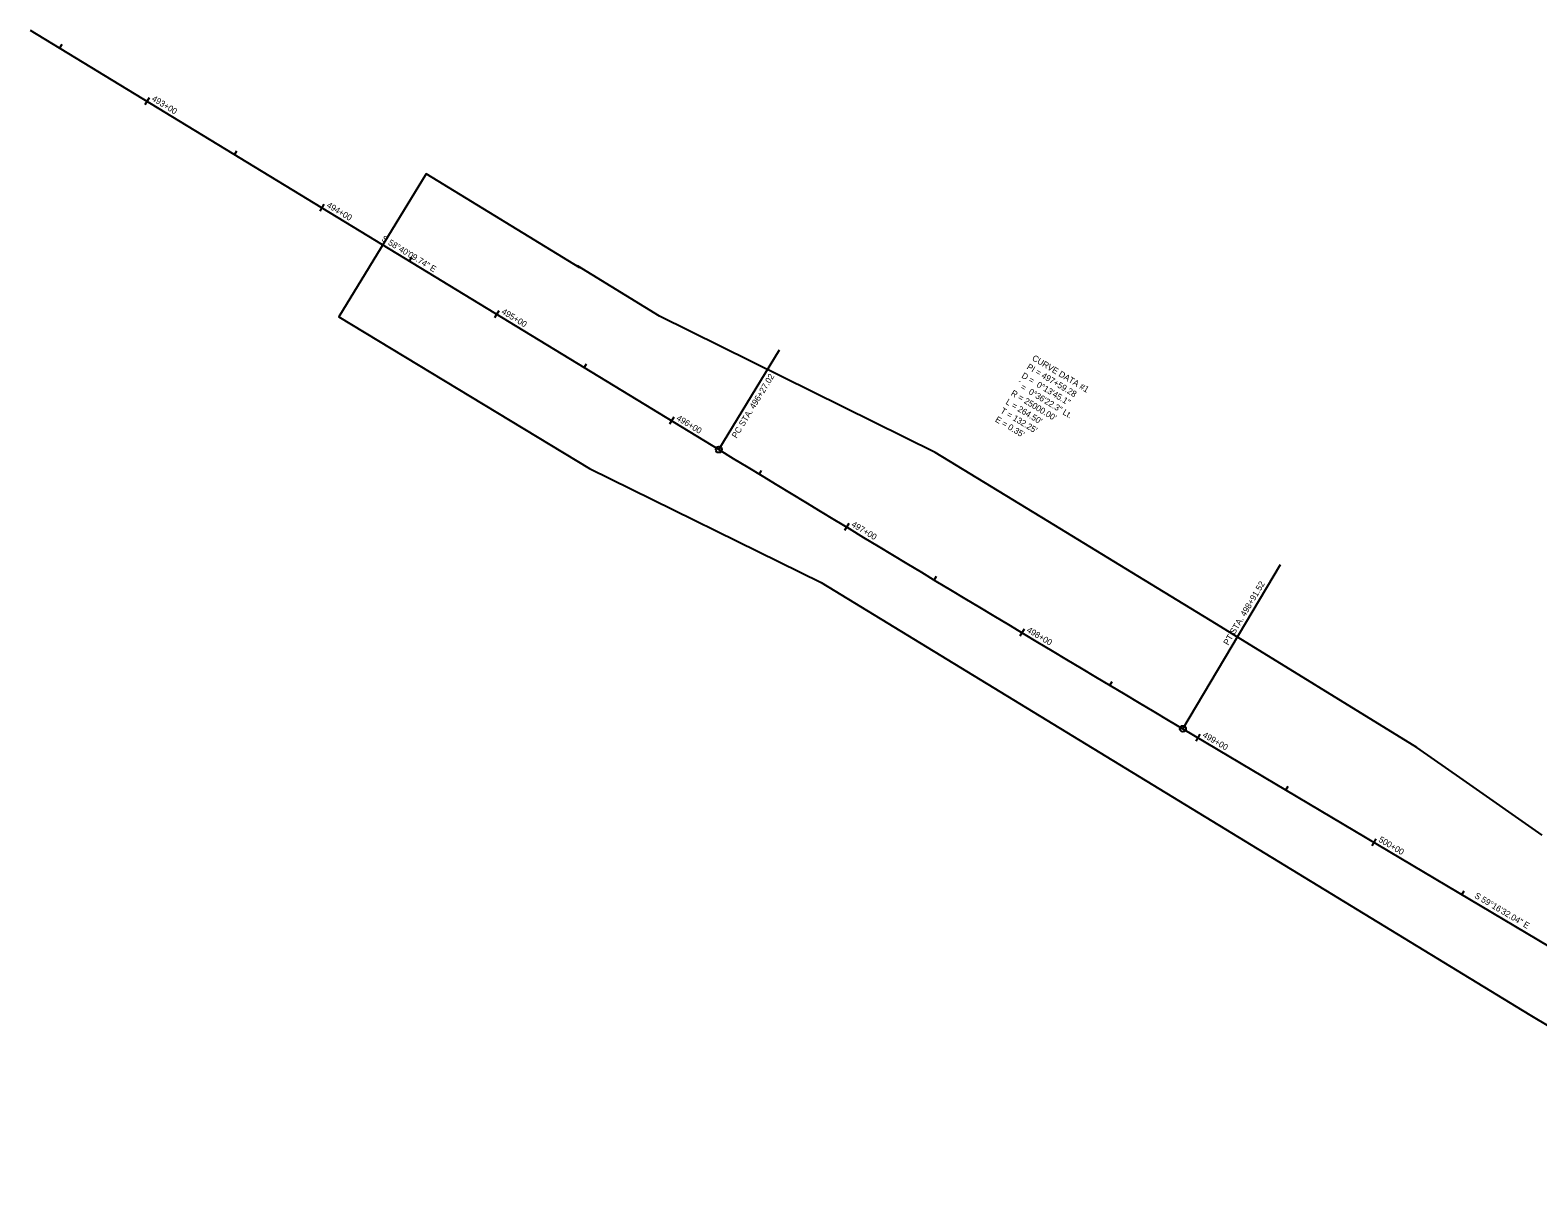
# Model space of a CAD drawing. Extents: x 1743277 to 1746745, y 462828 to 464839.
# Drawn here: x 1743277 to 1744013, y 464280 to 464839 of the extents above; entities that cross this region are included whole.
import ezdxf

# ---------------------------------------------------------------- set-up
doc = ezdxf.new("R2010")
doc.units = 0
for name, color, linetype in [('D_Roadway_Centerline', 7, 'Continuous'), ('D_Roadway_Centerline_Bearings', 7, 'Continuous'), ('D_Roadway_Centerline_CurveData', 7, 'Continuous'), ('D_Roadway_Centerline_Flags', 7, 'Continuous'), ('D_Roadway_Centerline_Text', 7, 'Continuous'), ('D_Roadway_Edge_TW', 7, 'Continuous')]:
    doc.layers.add(name, color=color, linetype=linetype)

msp = doc.modelspace()

# ---------------------------------------------------------------- linework, layer by layer
at = {"layer": 'D_Roadway_Centerline'}
for p, q in [((1743276.84, 464839.33), (1743613.24, 464634.55)), ((1743839.9, 464498.21), (1744191.04, 464289.52)), ((1743839.9, 464498.21), (1744191.04, 464289.52))]:
    msp.add_line(p, q, dxfattribs=at)
msp.add_arc((1756612.64, 485989.07), 25000, 238.669373, 239.275565, dxfattribs=at)
at = {"layer": 'D_Roadway_Centerline_Flags'}
for points in [[(1743613.24, 464634.55), (1743642.87, 464683.21)], [(1743839.9, 464498.21), (1743887.58, 464578.44)]]:
    msp.add_lwpolyline(points, dxfattribs=at)
for centre in [(1743613.24, 464634.55), (1743839.9, 464498.21)]:
    msp.add_circle(centre, 1.5, dxfattribs=at)
at = {"layer": 'D_Roadway_Centerline_Text'}
for points in [[(1743292.24, 464832.3), (1743291.2, 464830.59)], [(1743334.95, 464806.3), (1743332.87, 464802.88)], [(1743377.65, 464780.3), (1743376.61, 464778.59)], [(1743420.36, 464754.3), (1743418.28, 464750.89)], [(1743463.07, 464728.3), (1743462.03, 464726.6)], [(1743505.78, 464702.31), (1743503.7, 464698.89)], [(1743548.49, 464676.31), (1743547.45, 464674.6)], [(1743591.2, 464650.31), (1743589.12, 464646.89)], [(1743633.91, 464624.32), (1743632.87, 464622.61)], [(1743676.67, 464598.4), (1743674.6, 464594.98)], [(1743719.48, 464572.58), (1743718.44, 464570.86)], [(1743762.33, 464546.83), (1743760.28, 464543.4)], [(1743805.24, 464521.17), (1743804.22, 464519.46)], [(1743848.21, 464495.6), (1743846.16, 464492.16)], [(1743891.19, 464470.06), (1743890.17, 464468.34)], [(1743934.17, 464444.51), (1743932.13, 464441.07)], [(1743977.15, 464418.96), (1743976.13, 464417.25)]]:
    msp.add_lwpolyline(points, dxfattribs=at)
at = {"layer": 'D_Roadway_Edge_TW'}
for q in [(1743470.2, 464769.13), (1743544.26, 464724.3)]:
    msp.add_line((1743545.32, 464723.24), q, dxfattribs=at)
for points in [[(1743470.2, 464769.13), (1743427.68, 464699.28), (1743550.04, 464625.23), (1743663.29, 464569.56), (1744009.39, 464358.55), (1744096.94, 464306.36), (1744135.34, 464282.83), (1744151.41, 464265.42), (1744426.2, 464103.29), (1744481.09, 464065.93), (1744521.09, 464032.86), (1744582.5, 463969.09), (1744608.78, 463934.83), (1744633.67, 463900.81), (1744642.64, 463879.56)], [(1744015.47, 464446.22), (1743976.84, 464473.32), (1743954.23, 464489.03), (1743856.27, 464549.26), (1743814.95, 464574.53), (1743773.93, 464599.6), (1743718.97, 464633.17), (1743584.2, 464699.66), (1743544.26, 464724.3)]]:
    msp.add_lwpolyline(points, dxfattribs=at)

# ---------------------------------------------------------------- texts
at = {"layer": 'D_Roadway_Centerline_Bearings'}
for s, rotation, p in [('S 58%%d40\'09.74" E', 328.66937, (1743448.18, 464736.76)), ('S 59%%d16\'32.04" E', 329.27557, (1743982.04, 464415.91))]:
    msp.add_text(s, height=3, rotation=rotation, dxfattribs=at).set_placement(p)
at = {"layer": 'D_Roadway_Centerline_CurveData'}
for s, p in [('PI = 497+59.28', (1743763.37, 464674.13)), ('CURVE DATA #1', (1743765.95, 464678.41)), ('D =  0%%d13\'45.1"', (1743760.8, 464669.84)), ("R = 25000.00'", (1743755.64, 464661.27)), ('´ =  0%%d36\'22.3" Lt.', (1743758.22, 464665.56)), ("T = 132.25'", (1743750.49, 464652.7)), ("L = 264.50'", (1743753.06, 464656.99)), ("E = 0.35'", (1743747.91, 464648.42))]:
    msp.add_text(s, height=3, rotation=328.97247, dxfattribs=at).set_placement(p)
at = {"layer": 'D_Roadway_Centerline_Flags'}
for s, rotation, p in [('PC STA. 496+27.02', 58.66937, (1743621.89, 464639.81)), ('PT STA. 498+91.52', 59.27557, (1743862.04, 464538.74))]:
    msp.add_text(s, height=3, rotation=rotation, dxfattribs=at).set_placement(p)
at = {"layer": 'D_Roadway_Centerline_Text'}
for s, rotation, p in [('493+00', 328.66937, (1743335.97, 464805.09)), ('494+00', 328.66937, (1743421.38, 464753.1)), ('495+00', 328.66937, (1743506.8, 464701.1)), ('496+00', 328.66937, (1743592.22, 464649.1)), ('497+00', 328.83662, (1743677.69, 464597.2)), ('498+00', 329.06581, (1743763.36, 464545.63)), ('499+00', 329.27557, (1743849.24, 464494.4)), ('500+00', 329.27557, (1743935.2, 464443.31))]:
    msp.add_text(s, height=3, rotation=rotation, dxfattribs=at).set_placement(p)

doc.saveas('drawing.dxf')
